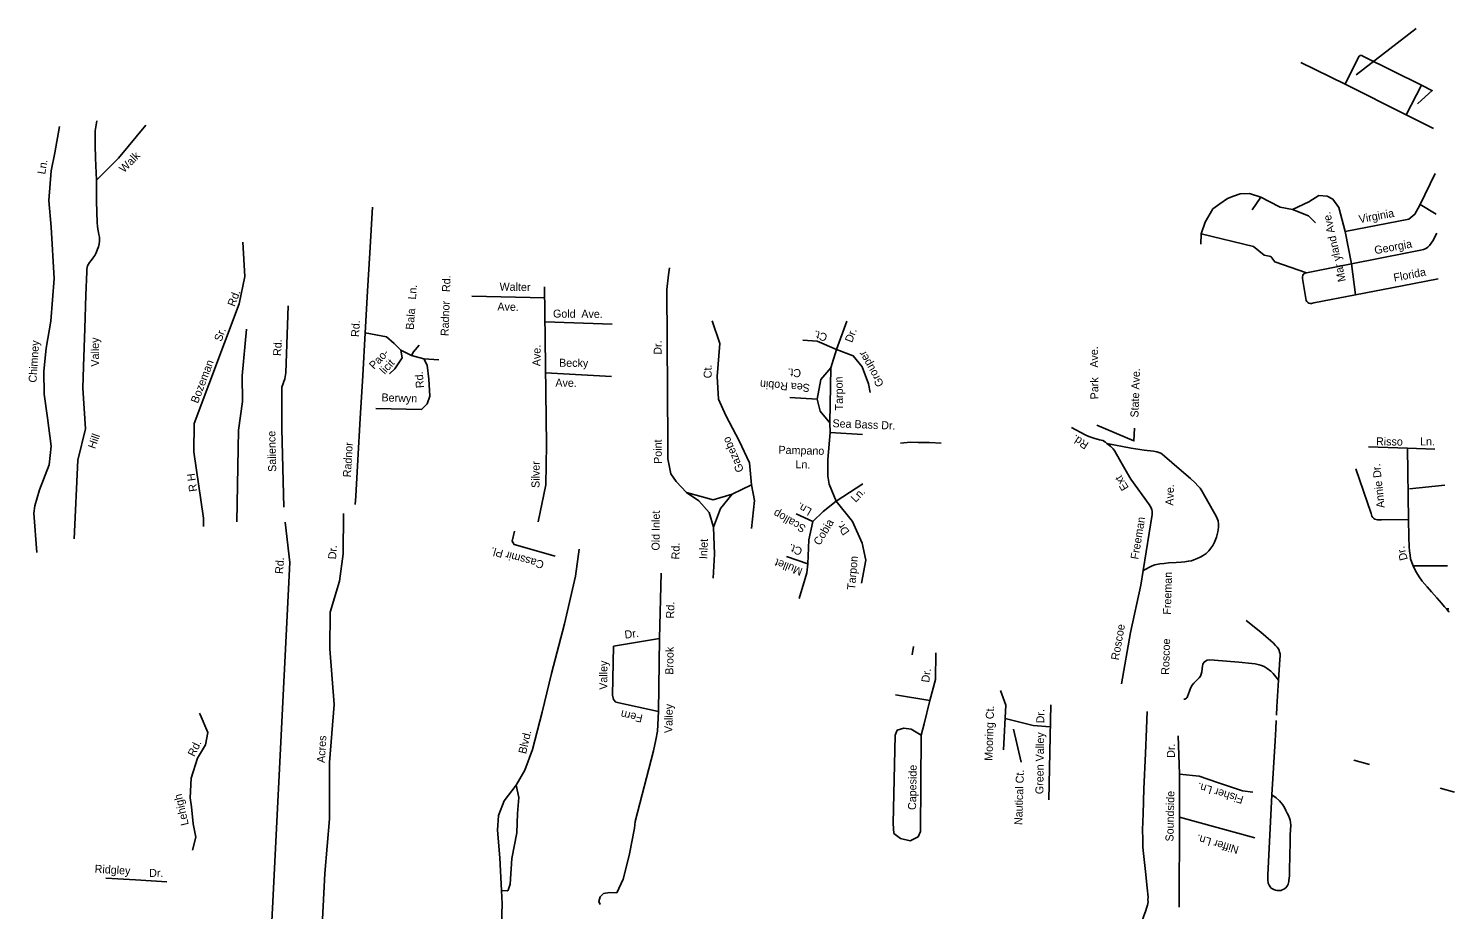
# Model space of a CAD drawing. Extents: x 2308163 to 2335412, y -96774 to 125428.
# Drawn here: x 2321495 to 2322225, y 33809 to 34260 of the extents above; entities that cross this region are included whole.
import ezdxf

# ---------------------------------------------------------------- set-up
doc = ezdxf.new("R2010")
doc.units = 0
doc.layers.add('Old_Level_10', color=7, linetype='Continuous')
doc.layers.add('Old_Level_35', color=7, linetype='Continuous')

msp = doc.modelspace()

# ---------------------------------------------------------------- linework, layer by layer
at = {"layer": 'Old_Level_10'}
for points in [[(2322205.74, 34260.48), (2322175.01, 34236.81)], [(2322214.08, 34228.98), (2322206.48, 34221.98)], [(2322061.4, 34055.75), (2322061.17, 34049.31), (2322042.09, 34057.39)], [(2322003.35, 33884.8), (2321999.42, 33901.7)]]:
    msp.add_lwpolyline(points, dxfattribs=at)
at = {"layer": 'Old_Level_35'}
for p, q in [((2322146.69, 34243.16), (2322169.32, 34231.98)), ((2322169.32, 34231.98), (2322200.7, 34216.23)), ((2322200.7, 34216.23), (2322208.55, 34231.4)), ((2322214.09, 34228.64), (2322208.55, 34231.4)), ((2322214.7, 34209.2), (2322200.7, 34216.23)), ((2322174.71, 34124.17), (2322172.58, 34139.98)), ((2321584.42, 34009.73), (2321579.57, 34043.66)), ((2322201.83, 34009.08), (2322201.3, 34045.53)), ((2321662.22, 34016.7), (2321662.47, 34021.02)), ((2321584.44, 34005.46), (2321584.42, 34009.73)), ((2321947.58, 33939.8), (2321948.16, 33944.04)), ((2322134.4, 33913.07), (2322135.17, 33926.76)), ((2322067.76, 33906.47), (2322067.93, 33910.73)), ((2322134.17, 33908.84), (2322134.4, 33913.07)), ((2322067.59, 33901.88), (2322067.76, 33906.47)), ((2322133.8, 33901.8), (2322133.54, 33895.66)), ((2322133.97, 33906.03), (2322133.8, 33901.8)), ((2322133.54, 33895.66), (2322131.9, 33868.06)), ((2322181.91, 33883.62), (2322173.83, 33885.69)), ((2322225.41, 33869.46), (2322218.13, 33871.5))]:
    msp.add_line(p, q, dxfattribs=at)
for points in [[(2322208.55, 34231.4), (2322178.78, 34246.13), (2322177.9, 34246.58), (2322177.16, 34246.7), (2322176.54, 34246.32), (2322176.28, 34245.81), (2322169.32, 34231.98)], [(2321508.34, 34196.75), (2321510.71, 34210.3)], [(2321529.66, 34182.79), (2321529.2, 34194.06), (2321528.98, 34200.68), (2321528.9, 34203.43), (2321529.03, 34208.06), (2321529.78, 34213.29)], [(2321554.98, 34211.06), (2321540.94, 34194.02), (2321529.66, 34182.79)], [(2321499.01, 33992.15), (2321497.53, 34012.27), (2321497.98, 34016.06), (2321500.48, 34024.22), (2321505.37, 34037.05), (2321506.33, 34046.53), (2321504.61, 34061.17), (2321502.81, 34073.28), (2321502.58, 34085.02), (2321503.93, 34096.71), (2321506.32, 34110.57), (2321508.02, 34132.39), (2321506.39, 34158.77), (2321505.28, 34172.44), (2321506.43, 34187.62), (2321508.34, 34196.75)], [(2322207.66, 34170.02), (2322215.43, 34186.25)], [(2321522.72, 34076.25), (2321522.99, 34087.4), (2321523.59, 34106.9), (2321524.12, 34124), (2321524.67, 34135.87), (2321524.68, 34137.26), (2321524.78, 34138.1), (2321524.98, 34139.01), (2321525.51, 34139.85), (2321526.06, 34140.59), (2321526.92, 34141.7), (2321527.83, 34142.94), (2321528.71, 34144.25), (2321529.42, 34145.61), (2321530.19, 34147.5), (2321530.59, 34148.75), (2321530.93, 34150.19), (2321531.11, 34151.5), (2321531.11, 34152.55), (2321531.1, 34153.61), (2321530.91, 34154.92), (2321530.72, 34155.99), (2321530.32, 34157.67), (2321530.09, 34159.18), (2321529.9, 34160.9), (2321529.66, 34172.03), (2321529.66, 34182.79)], [(2322172.58, 34139.98), (2322169.4, 34156.48), (2322166.11, 34168.8), (2322163.07, 34173.14), (2322160.2, 34174.57), (2322155.97, 34174.98), (2322150.81, 34171.71), (2322142.45, 34167.76), (2322136.12, 34169.03), (2322130.38, 34171.89), (2322126.22, 34174.15), (2322120.44, 34175.94), (2322115.66, 34175.84), (2322112.17, 34174.64), (2322109.2, 34173.41), (2322105.13, 34170.63), (2322101.59, 34168.1), (2322097.64, 34161.34), (2322095.57, 34155.32), (2322095.39, 34150.02)], [(2322126.22, 34174.15), (2322121.75, 34167.67)], [(2322216.09, 34165.37), (2322207.81, 34170.33)], [(2321662.47, 34021.02), (2321663.53, 34039.59), (2321664.78, 34060.83), (2321666.08, 34082.81), (2321667.35, 34104.65), (2321668.49, 34126.01), (2321669.73, 34145.61), (2321671.02, 34169.01)], [(2322142.45, 34167.76), (2322150.57, 34164.56), (2322154.16, 34160.99)], [(2322169.4, 34156.48), (2322202.1, 34162.78), (2322205.11, 34165.33), (2322207.66, 34170.02)], [(2322172.58, 34139.98), (2322201.11, 34145.68), (2322207.15, 34146.77), (2322208.79, 34147.11), (2322209.55, 34147.34), (2322210.43, 34147.71), (2322211, 34148.04), (2322211.69, 34148.54), (2322212.53, 34149.32), (2322213.49, 34150.49), (2322214.26, 34151.73), (2322216.39, 34155.66)], [(2321579.57, 34043.66), (2321579.69, 34058.14), (2321602.8, 34119.51), (2321605.57, 34133.52), (2321604.65, 34151.1)], [(2322095.57, 34155.32), (2322122.42, 34148.82), (2322127.84, 34144.39), (2322131.27, 34143.74), (2322133.3, 34141.02), (2322149.51, 34135.32)], [(2321845.57, 33979.04), (2321846.36, 33991.29), (2321845.75, 34005.03), (2321843.48, 34012.69), (2321838.27, 34018.64), (2321831.91, 34022.84), (2321826.68, 34028.43), (2321823.93, 34032.5), (2321822.39, 34040.13), (2321822.31, 34048.44), (2321821.77, 34126.81), (2321822.75, 34134.36), (2321823.23, 34137.95)], [(2322174.71, 34124.17), (2322153.35, 34119.94), (2322152.08, 34119.71), (2322151.53, 34119.71), (2322150.85, 34119.87), (2322150.34, 34120.13), (2322149.74, 34120.64), (2322149.35, 34121.27), (2322147.53, 34132.46), (2322147.55, 34133.32), (2322147.69, 34133.95), (2322147.95, 34134.57), (2322148.2, 34134.86), (2322148.85, 34135.19), (2322149.51, 34135.32), (2322172.58, 34139.98)], [(2321755.95, 34007.76), (2321759.85, 34026.76), (2321760.2, 34047.33), (2321759.22, 34128.12)], [(2322217.13, 34132.26), (2322198.59, 34128.71), (2322174.71, 34124.17)], [(2321722, 34123.39), (2321759.29, 34122.48)], [(2321625.55, 34015.33), (2321624.59, 34055.44), (2321624.6, 34076.74), (2321626.19, 34081.02), (2321626.66, 34084.07), (2321627.85, 34118.52)], [(2321601.49, 34007.89), (2321602.34, 34054.76), (2321604.48, 34069.49), (2321604.21, 34082.68), (2321606.47, 34106.43)], [(2321667.35, 34104.65), (2321678.28, 34102.51), (2321682.14, 34099.13), (2321685.63, 34095.76), (2321686.22, 34091.77), (2321682.41, 34086.12), (2321679.8, 34083.69)], [(2321759.44, 34110.19), (2321793.77, 34109)], [(2321865.29, 34026.74), (2321864.23, 34037.97), (2321858.84, 34049.35), (2321852.06, 34062.22), (2321848.37, 34070.65), (2321847.69, 34082.23), (2321849, 34099.15), (2321845.06, 34110.84)], [(2321908.65, 34018.38), (2321904.97, 34027.18), (2321904.39, 34031.17), (2321904.33, 34039.84), (2321905.52, 34053.51), (2321905.33, 34058.58), (2321905.94, 34086.72), (2321908.79, 34096.01), (2321914, 34110.63)], [(2321685.63, 34095.76), (2321690.96, 34093.05), (2321692.1, 34094.82), (2321695.04, 34098.37)], [(2321908.79, 34096.01), (2321898.83, 34100.32), (2321891.62, 34100.93)], [(2321697.41, 34091.38), (2321699.1, 34088.08), (2321699.93, 34080.83), (2321700.35, 34072.15), (2321699.14, 34068.22), (2321696.15, 34065.43), (2321672.68, 34065.88)], [(2321690.96, 34093.05), (2321697.41, 34091.38), (2321704.97, 34090.76)], [(2321908.79, 34096.01), (2321917.36, 34092.82), (2321921.86, 34087.25), (2321925.17, 34078.47), (2321926.1, 34074.11)], [(2321759.76, 34084.18), (2321793.56, 34082.27)], [(2321905.94, 34086.72), (2321900.68, 34080.76), (2321898.89, 34070.71), (2321900.48, 34064.52), (2321905.33, 34058.58)], [(2321522.72, 34076.25), (2321524.08, 34055.43), (2321520.04, 34039.4), (2321518.17, 33999.1)], [(2321898.89, 34070.71), (2321884.83, 34071.56)], [(2321905.52, 34053.51), (2321922.11, 34052.58)], [(2322029.13, 34056.13), (2322036.16, 34052.45), (2322038.03, 34051.54), (2322040.63, 34050.71), (2322043.47, 34049.91), (2322045.21, 34049.48), (2322046.59, 34048.71), (2322047.31, 34047.94)], [(2321962.36, 34048.04), (2321956.36, 34048.4), (2321950.67, 34048.44), (2321946.72, 34048.57), (2321941.49, 34048.12)], [(2322065.87, 33982.97), (2322070.57, 34011.51), (2322070.59, 34012.24), (2322070.48, 34013.23), (2322070.37, 34014.03), (2322070.25, 34014.54), (2322070.06, 34015.03), (2322068.95, 34016.77), (2322059.62, 34029.76), (2322057.94, 34032.56), (2322054.47, 34038.63), (2322052.3, 34042.43), (2322051.47, 34043.96), (2322050.5, 34045.23), (2322049.39, 34046.39), (2322047.31, 34047.94)], [(2322047.31, 34047.94), (2322059.76, 34045.62), (2322066.49, 34044.61), (2322071.23, 34044), (2322072.97, 34043.7), (2322073.96, 34043.42), (2322074.94, 34042.99), (2322075.7, 34042.5), (2322076.8, 34041.48), (2322084.39, 34034.9), (2322090.14, 34030.03), (2322092.59, 34027.83), (2322093.95, 34026.32), (2322095.04, 34025.03), (2322096.01, 34023.77), (2322097.44, 34020.97), (2322102.01, 34013.1), (2322103.31, 34010.71), (2322103.79, 34009.5), (2322104.26, 34008.31), (2322104.56, 34006.65), (2322104.55, 34005.05), (2322104.39, 34003.8), (2322104.21, 34002.67), (2322103.51, 33999.99), (2322102.49, 33997.46), (2322101.58, 33995.73), (2322100.66, 33994.38), (2322099.5, 33992.91), (2322098.75, 33992.17), (2322098.1, 33991.58), (2322096.62, 33990.54), (2322095.17, 33989.76), (2322093.58, 33988.99), (2322091.84, 33988.31), (2322090.73, 33987.91), (2322089.03, 33987.62), (2322087.25, 33987.32), (2322085.31, 33987.21), (2322082.74, 33987.05), (2322078.85, 33986.77), (2322076.72, 33986.57), (2322074.45, 33986.25), (2322071.95, 33985.81), (2322070.56, 33985.35), (2322065.87, 33982.97)], [(2322181.41, 34046.21), (2322201.3, 34045.53)], [(2322201.3, 34045.53), (2322215.35, 34045.04)], [(2322201.83, 34009.08), (2322188.06, 34008.91), (2322186.56, 34008.82), (2322186.07, 34008.84), (2322185.31, 34008.98), (2322184.61, 34009.16), (2322184.1, 34009.47), (2322183.5, 34010.06), (2322183.11, 34010.77), (2322182.77, 34012.04), (2322174.93, 34035)], [(2321845.75, 34005.03), (2321849.33, 34014.65), (2321855.37, 34022.03), (2321865.29, 34026.74), (2321866.82, 34018.74), (2321865.24, 34004.35)], [(2321908.65, 34018.38), (2321922.32, 34027.3)], [(2322220.46, 34026.63), (2322202.44, 34024.8)], [(2321831.91, 34022.84), (2321845.51, 34019.12), (2321855.37, 34022.03)], [(2321896.72, 34007.96), (2321901.96, 34013.2), (2321908.65, 34018.38), (2321916.96, 34007.99), (2321922, 33996.98), (2321923.87, 33988.25), (2321921.65, 33976.41)], [(2321642.5, 33747.31), (2321646.65, 33827.81), (2321648.99, 33855.68), (2321649.06, 33884.54), (2321651.46, 33914.24), (2321649.24, 33942.73), (2321649.43, 33961.51), (2321654.1, 33977.38), (2321655.96, 33991.52), (2321656.22, 34012.13)], [(2321894.17, 33986.39), (2321894.6, 33998.65), (2321896.72, 34007.96), (2321888.19, 34011.87)], [(2321616.99, 33752.13), (2321628.75, 33986.96), (2321626.26, 34007.67)], [(2321764.62, 33990.29), (2321743.61, 33996.25), (2321742.61, 33997.86), (2321743.73, 34003.13)], [(2322204.24, 33985.38), (2322203.54, 33987.04), (2322202.95, 33988.92), (2322202.62, 33990.68), (2322202.32, 33992.93), (2322202.12, 33995.07), (2322201.98, 34000.09), (2322201.83, 34009.08)], [(2321749.41, 33724.04), (2321745.7, 33730.45), (2321743.15, 33732.37), (2321737.47, 33765.29), (2321736.99, 33773.95), (2321736.6, 33785.48), (2321737.52, 33812.15), (2321737.23, 33818.97), (2321736.24, 33835.76), (2321735.15, 33849.93), (2321735.68, 33857.51), (2321738.55, 33865), (2321744.59, 33872.91), (2321749.05, 33880.61), (2321753.08, 33891.2), (2321757.94, 33910.41), (2321762.81, 33930.14), (2321769.45, 33955.57), (2321775.01, 33979.99), (2321776.9, 33993.77)], [(2321889.58, 33968.49), (2321893.65, 33981.71), (2321894.17, 33986.39), (2321883.1, 33990.02)], [(2321818.88, 33981.46), (2321818.13, 33948.02), (2321794.55, 33944.12), (2321794.07, 33919.01), (2321794.52, 33916.77), (2321795.78, 33915.41), (2321817.5, 33910.74), (2321818.13, 33948.02)], [(2322054.73, 33924.82), (2322059.35, 33951.23), (2322064.68, 33975.36), (2322065.87, 33982.97)], [(2322222.51, 33961.58), (2322222.44, 33961.69), (2322221.35, 33963.23), (2322220.38, 33964.37), (2322218.81, 33966.14), (2322216.36, 33968.84), (2322213.7, 33971.92), (2322211.49, 33974.47), (2322208.89, 33977.43), (2322207.39, 33979.68), (2322205.92, 33981.97), (2322204.97, 33983.74), (2322204.24, 33985.38)], [(2322221.76, 33985.36), (2322221.13, 33985.36), (2322204.24, 33985.38)], [(2322221.35, 33963.23), (2322222.45, 33963.3)], [(2322135.17, 33926.76), (2322135.94, 33937.38), (2322136.09, 33939.25), (2322136.07, 33940.19), (2322135.84, 33941.15), (2322135.55, 33942.01), (2322135.17, 33942.81), (2322134.57, 33943.67), (2322133.75, 33944.57), (2322132.51, 33945.85), (2322131.28, 33946.87), (2322126.13, 33951.25), (2322118.66, 33957.3)], [(2321959.68, 33940.73), (2321959.5, 33927.1), (2321956.61, 33916.37), (2321939.07, 33919.24)], [(2322086.77, 33916.98), (2322087.17, 33917.03), (2322087.62, 33917.26), (2322088.05, 33917.53), (2322088.38, 33917.9), (2322088.7, 33918.37), (2322089.11, 33919.75), (2322089.63, 33921.1), (2322090.18, 33922.58), (2322091.09, 33924.19), (2322091.87, 33925.19), (2322093.27, 33926.64), (2322094.56, 33927.99), (2322095.21, 33928.86), (2322095.64, 33929.84), (2322096.02, 33931.08), (2322096.18, 33932.57), (2322096.37, 33934.05), (2322096.49, 33934.75), (2322096.65, 33935.36), (2322097.14, 33936), (2322097.88, 33936.56), (2322098.65, 33936.91), (2322099.66, 33937.12), (2322102.28, 33936.93), (2322114.89, 33935.88), (2322121.62, 33935.22), (2322123.36, 33935.05), (2322125.37, 33934.65), (2322126.61, 33934.22), (2322127.98, 33933.7), (2322129.52, 33932.7), (2322131.36, 33931.27), (2322132.51, 33930.13), (2322135.17, 33926.76)], [(2321956.61, 33916.37), (2321953.68, 33904.38), (2321952.22, 33898.64), (2321951.78, 33849.28), (2321950.68, 33846.55), (2321946.57, 33844.42), (2321941.57, 33845.6), (2321938.13, 33848.24), (2321937.8, 33853.29), (2321938.86, 33898.6), (2321939.95, 33901.08), (2321943.27, 33902.22), (2321947.03, 33901.59), (2321952.22, 33898.64)], [(2321992.88, 33921.42), (2321995.6, 33914.02), (2321994.31, 33891.14)], [(2321582.41, 33909.9), (2321582.7, 33909.24), (2321586.64, 33900.01), (2321585.51, 33893.66), (2321581.31, 33886.8), (2321578.21, 33876.56), (2321577.56, 33866.54), (2321578.32, 33861.95), (2321579.23, 33853.09), (2321580.52, 33846.35), (2321578.77, 33839.71)], [(2321817.5, 33910.74), (2321817.15, 33900.54), (2321816.21, 33896.12), (2321815.1, 33890.53), (2321805.6, 33854.42), (2321805.22, 33850.89), (2321802.67, 33837.76), (2321802.2, 33835.55), (2321799.47, 33824.78), (2321796.22, 33817.82), (2321792.68, 33817.95), (2321789.39, 33817.41), (2321787.63, 33815.76), (2321787.03, 33813.43), (2321787.76, 33811.83)], [(2322017.62, 33865.4), (2322018.52, 33914.06)], [(2321995.21, 33907.03), (2322009.61, 33903.46), (2322018.31, 33902.87)], [(2322065.1, 33801.57), (2322065.4, 33802.63), (2322065.82, 33804.5), (2322066.22, 33806.12), (2322067.03, 33808.34), (2322067.72, 33810.45), (2322068.12, 33811.58), (2322068.26, 33812.44), (2322068.4, 33813.18), (2322068.29, 33814.31), (2322068.45, 33815.56), (2322067.95, 33820.45), (2322067.15, 33828.73), (2322066.12, 33838.01), (2322065.7, 33841.15), (2322065.68, 33845.27), (2322065.55, 33850.14), (2322065.86, 33858.26), (2322066.29, 33871.01), (2322067.1, 33889.12), (2322067.59, 33901.88)], [(2322084.49, 33878.65), (2322083.84, 33898.3)], [(2322084.27, 33810.49), (2322084.53, 33856.63), (2322084.49, 33878.65)], [(2322084.49, 33878.65), (2322094.54, 33877.51), (2322103.98, 33874.26), (2322116.84, 33870.11), (2322122.13, 33869.39)], [(2321744.59, 33872.91), (2321745.95, 33866.63), (2321745.41, 33858.53), (2321745.06, 33848.6), (2321742.51, 33835.33), (2321741.54, 33822.28), (2321740.64, 33819.17), (2321740.11, 33818.92), (2321737.23, 33818.97)], [(2322131.9, 33868.06), (2322129.76, 33826.85), (2322129.78, 33824.41), (2322129.93, 33822.79), (2322130.38, 33821.71), (2322130.9, 33820.95), (2322131.56, 33820.28), (2322132.09, 33819.91), (2322132.83, 33819.51), (2322133.66, 33819.22), (2322134.56, 33818.98), (2322135.34, 33818.95), (2322135.81, 33818.97), (2322136.55, 33819.09), (2322137.1, 33819.28), (2322137.92, 33819.63), (2322138.49, 33820.01), (2322138.98, 33820.38), (2322139.51, 33821), (2322139.9, 33821.59), (2322140.16, 33822.21), (2322140.38, 33823.01), (2322140.5, 33823.6), (2322140.62, 33824.36), (2322140.74, 33825.2), (2322140.89, 33826.7), (2322140.93, 33828.46), (2322140.96, 33829.57), (2322141.18, 33843.96), (2322141.26, 33847.59), (2322141.41, 33850.15), (2322141.51, 33852.33), (2322141.39, 33854.09), (2322141.16, 33854.99), (2322140.85, 33856.09), (2322140.35, 33857.42), (2322139.75, 33858.63), (2322139.07, 33860.02), (2322138.43, 33861.14), (2322137.39, 33862.82), (2322136.55, 33863.96), (2322135.81, 33864.86), (2322134.04, 33866.41), (2322131.9, 33868.06)], [(2322084.53, 33856.63), (2322123.18, 33846.02)], [(2321534.42, 33825.41), (2321549.62, 33824.52), (2321565.72, 33823.42)]]:
    msp.add_lwpolyline(points, dxfattribs=at)

# ---------------------------------------------------------------- texts
at = {"layer": 'Old_Level_10'}
for s, rotation, p in [('Ln.', 80.18579, (2321503.33, 34185.59)), ('Walk', 45.38719, (2321543.72, 34186.33)), ('Mar yland Ave.', 102.8292, (2322169.8, 34131.23)), ('Virginia', 10.49306, (2322176.78, 34160.77)), ('Georgia', 10.48126, (2322184.75, 34144.85)), ('Florida', 11.00888, (2322194.6, 34130.82)), ('Bala   Ln.', 85.75423, (2321692.14, 34106.07)), ('Radnor   Rd.', 88.15233, (2321710.02, 34102.92)), ('Walter', 358.73813, (2321736.11, 34126.31)), ('Bozeman       Sr.        Rd.', 69.19482, (2321581.58, 34068.2)), ('Ave.', 358.73813, (2321735.01, 34116.08)), ('Gold', 359.40928, (2321763.52, 34112.45)), ('Ave.', 359.40928, (2321778.03, 34112.33)), ('Rd.', 86.93568, (2321664.15, 34102.41)), ('Ct.', 163.82832, (2321904.44, 34104)), ('Dr.', 69.38486, (2321916.75, 34099.32)), ('Chimney', 86.24859, (2321498.88, 34079.03)), ('Valley', 90.4143, (2321530.96, 34087.34)), ('Rd.', 87.60863, (2321624.22, 34092.7)), ('Ave.', 89.52292, (2321757.1, 34087.53)), ('Dr.', 89.4605, (2321819.18, 34093.42)), ('Ave.', 90.57036, (2322042.84, 34086.82)), ('Pao-', 46.90689, (2321671.86, 34085.63)), ('licit', 46.90689, (2321677.29, 34083.08)), ('Becky', 359.39522, (2321766.63, 34087.27)), ('Grouper', 119.42301, (2321933.26, 34078.35)), ('Rd.', 94.31649, (2321697.43, 34076.45)), ('Ct.', 91.0081, (2321844.87, 34081.38)), ('Ct.', 175.71507, (2321890.78, 34085.9)), ('State Ave.', 88.02472, (2322063.45, 34061.2)), ('Ave.', 359.39522, (2321764.74, 34077.04)), ('       Sea Robin ', 175.71507, (2321905.89, 34077.57)), ('Tarpon', 90.96878, (2321912.18, 34064.9)), ('Park', 90.57036, (2322043, 34070.57)), ('Berwyn', 358.1695, (2321675.61, 34069.54)), ('Salience', 91.3925, (2321621.74, 34033.47)), ('Sea Bass Dr.', 357.76224, (2321906.67, 34056.3)), ('Hill ', 70.57017, (2321528.96, 34044.92)), ('Radnor', 86.71925, (2321659.93, 34030.56)), ('Point', 90.4182, (2321819.31, 34037.54)), ('Gazebo', 113.08233, (2321861.45, 34034.22)), ('Pampano ', 358.56772, (2321879.02, 34042.69)), ('Rd.', 147.56716, (2322038.35, 34048.15)), ('Risso', 359.23122, (2322185.2, 34047.04)), ('Ln.', 359.78718, (2322207.79, 34046.99)), ('Silver', 89.52253, (2321756.59, 34025.18)), ('Ln.', 358.56772, (2321887.72, 34035.29)), ('R H', 97.68715, (2321581.22, 34023.53)), ('Ext', 120.87874, (2322058.68, 34025.32)), ('Annie Dr.', 96.08257, (2322189.68, 34015.1)), ('Ave.', 88.36506, (2322081.37, 34016.09)), ('Ln.', 150.38519, (2321896.53, 34014.3)), ('Ln.', 45.7345, (2321918.55, 34017.5)), ('Old Inlet', 89.48366, (2321818.12, 33993.12)), ('Scallop ', 150.38519, (2321893.51, 34005.54)), ('Freeman', 80.65612, (2322063.4, 33988.38)), ('Cobia', 58.95245, (2321900.21, 33995.44)), ('Dr.', 125.53608, (2321915.7, 34002.82)), ('Dr.', 85.98926, (2321652.36, 33988.54)), ('Cassmir Pl.', 164.86716, (2321759.23, 33987.64)), ('Rd.', 89.48366, (2321828.33, 33988.58)), ('Inlet', 88.02472, (2321842.53, 33988.69)), ('Ct.', 159.12015, (2321891.69, 33994.24)), ('Dr.', 104.75812, (2322201.5, 33988.62)), ('Rd.', 85.89384, (2321625.17, 33981.03)), ('Mullet', 159.12015, (2321891.78, 33983.9)), ('Tarpon', 84.96368, (2321918.24, 33972.88)), ('Freeman', 88.36506, (2322080.09, 33960.23)), ('Rd.', 89.1148, (2321825.59, 33958.33)), ('Dr.', 7.31703, (2321800.45, 33947.99)), ('Roscoe', 79.98655, (2322053.37, 33936.76)), ('Brook', 89.11451, (2321825.14, 33929.52)), ('Roscoe ', 88.36506, (2322079.2, 33929.43)), ('Valley', 89.34598, (2321791.29, 33921.8)), ('Dr.', 82.12929, (2321956.25, 33925.34)), ('Valley', 89.11338, (2321824.68, 33899.62)), ('Fern', 167.80014, (2321809.77, 33909)), ('Mooring Ct.', 88.26116, (2321988.68, 33885.38)), ('Green Valley   Dr.', 89.29644, (2322014.76, 33868.34)), ('Blvd.', 76.55392, (2321749.67, 33888.71)), ('Rd.', 63.66991, (2321579.8, 33887.22)), ('Acres', 86.63312, (2321646.61, 33884.28)), ('Dr.', 89.64489, (2322082.13, 33886.95)), ('Capeside', 89.10122, (2321949.52, 33860.23)), ('Nautical Ct.', 88.02472, (2322003.9, 33852.5)), ('Fisher Ln.', 162.94304, (2322117.67, 33867.23)), ('Lehigh', 103.2557, (2321576.97, 33852.79)), ('Soundside ', 88.85475, (2322081.4, 33844.09)), ('Niffer Ln.', 163.63217, (2322115.23, 33841.56)), ('Ridgley', 356.74322, (2321528.62, 33828.13)), ('Dr.', 359.02815, (2321556.57, 33826.02))]:
    msp.add_text(s, height=4.101, rotation=rotation, dxfattribs=at).set_placement(p)

doc.saveas('drawing.dxf')
